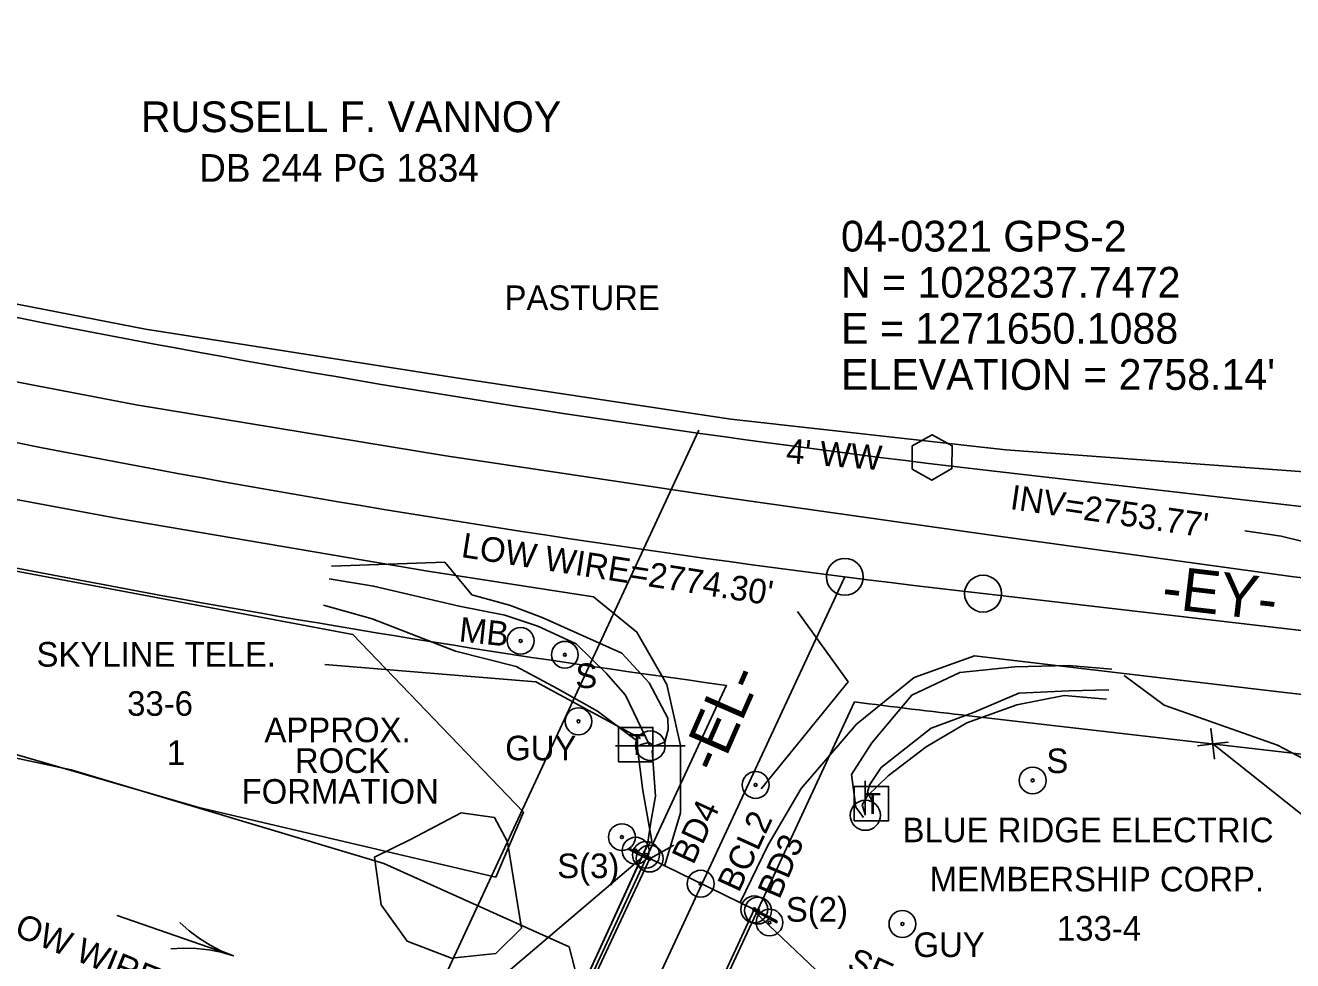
# Model space of a CAD drawing. Extents: x 1271070 to 1271913, y 1027587 to 1028435.
# Drawn here: x 1271502.6 to 1271708.8, y 1028155.9 to 1028308 of the extents above; entities that cross this region are included whole.
import ezdxf

# ---------------------------------------------------------------- set-up
doc = ezdxf.new("R2010")
doc.units = 0
for name, color, linetype in [('CTL Primary Horizontal and Vertical CELL', 7, 'Continuous'), ('CTL Primary Horizontal and Vertical Text', 7, 'Continuous'), ('Exist Horizontal Alignment', 7, 'Continuous'), ('Exist Horizontal Alignment Direction Label', 7, 'Continuous'), ('Exist Horizontal Alignment Point', 7, 'Continuous'), ('Exist Hydro Jurisdictional Stream or Body of Water', 7, 'Continuous'), ('Exist Hydro River Flow Arrow CELL', 7, 'Continuous'), ('Exist Other Culture Anchor (Guy Wire) CELL', 7, 'Continuous'), ('Exist Other Culture Anchor (Guy Wire) Text', 7, 'Continuous'), ('Exist Other Culture Area Outline', 7, 'Continuous'), ('Exist Other Culture Area Outline Text', 7, 'Continuous'), ('Exist Other Culture Fence Line', 7, 'Continuous'), ('Exist Other Culture Fence Line Text', 7, 'Continuous'), ('Exist Other Culture Located Object CELL', 7, 'Continuous'), ('Exist Other Culture Located Object Leader', 7, 'Continuous'), ('Exist Other Culture Located Object Text', 7, 'Continuous'), ('Exist Other Culture Sign CELL', 7, 'Continuous'), ('Exist Other Culture Sign Text', 7, 'Continuous'), ('Exist Property Corner CELL', 7, 'Continuous'), ('Exist Property Deed Book Text', 7, 'Continuous'), ('Exist Property Line', 7, 'Continuous'), ('Exist Property Owner Text', 7, 'Continuous'), ('Exist Right of Way Line', 7, 'Continuous'), ('Exist Roads EOP', 7, 'Continuous'), ('Exist Roads Soil', 7, 'Continuous'), ('Exist Structure Major Bridge WW', 7, 'Continuous'), ('Exist Structure Major Deck Tunnel Box Culvert', 7, 'Continuous'), ('Exist Structure Minor Pipes CMP 18 Inch Invert', 7, 'Continuous'), ('Exist Structure Minor Pipes CMP 18 Inch Leader', 7, 'Continuous'), ('Exist Utilities Other Located Object CELL', 7, 'Continuous'), ('Exist Utilities Other Located Object Leader', 7, 'Continuous'), ('Exist Utilities Other Located Object Text', 7, 'Continuous'), ('Exist Utilities Power Pole CELL', 7, 'Continuous'), ('Exist Utilities Power Pole Text', 7, 'Continuous'), ('Exist Utilities Telephone Pedestal CELL', 7, 'Continuous'), ('Exist Utilities Telephone Pole CELL', 7, 'Continuous'), ('Exist Utilities Telephone Pole Leader', 7, 'Continuous'), ('Exist Utilities Telephone Pole Text', 7, 'Continuous'), ('Exist Utilities Telephone UG Cable SUE LOS C', 7, 'Continuous'), ('Exist Vegetation Woods Line', 7, 'Continuous'), ('Exist Vegetation Woods Line Text', 7, 'Continuous')]:
    doc.layers.add(name, color=color, linetype=linetype)

msp = doc.modelspace()

# ---------------------------------------------------------------- linework, layer by layer
at = {"layer": 'CTL Primary Horizontal and Vertical CELL'}
msp.add_line((1271650.11, 1028237.75), (1271650.11, 1028237.75), dxfattribs=at)
msp.add_lwpolyline([(1271646.88, 1028239.62), (1271650.13, 1028241.43), (1271653.38, 1028239.64), (1271653.33, 1028235.92), (1271650.08, 1028234.03), (1271646.88, 1028235.84)], close=True, dxfattribs=at)
at = {"layer": 'Exist Horizontal Alignment'}
for p, q in [((1271563.09, 1028136.63), (1271612.17, 1028242.18)), ((1271586.84, 1028112.76), (1271635.92, 1028218.31)), ((1271812.09, 1028197.82), (1271658.4, 1028215.59))]:
    msp.add_line(p, q, dxfattribs=at)
msp.add_arc((1271888.09, 1030202.35), 2000, 256.46543, 263.40535, dxfattribs=at)
at = {"layer": 'Exist Horizontal Alignment Point'}
for centre in [(1271635.92, 1028218.31), (1271658.4, 1028215.58)]:
    msp.add_circle(centre, 3, dxfattribs=at)
at = {"layer": 'Exist Hydro Jurisdictional Stream or Body of Water'}
msp.add_lwpolyline([(1271304.7, 1028214.03), (1271358.66, 1028206.9), (1271411.07, 1028198.58), (1271456, 1028198.43), (1271510.08, 1028186.94), (1271560.93, 1028171.69), (1271591.08, 1028158.12), (1271592.88, 1028151.16), (1271591.46, 1028148.01), (1271611.09, 1028139.56), (1271653.5, 1028127.81), (1271692.8, 1028106.61), (1271731.61, 1028109.95), (1271774.25, 1028123.55), (1271810.26, 1028145.38)], dxfattribs=at)
at = {"layer": 'Exist Hydro River Flow Arrow CELL'}
msp.add_line((1271527.02, 1028159.94), (1271527.02, 1028159.94), dxfattribs=at)
msp.add_lwpolyline([(1271527.77, 1028162.1), (1271529.29, 1028160.73), (1271530.95, 1028159.49), (1271532.72, 1028158.37), (1271534.56, 1028157.4), (1271536.47, 1028156.66), (1271517.57, 1028163.21), (1271536.47, 1028156.66), (1271534.51, 1028157.26), (1271532.47, 1028157.64), (1271530.39, 1028157.86), (1271528.31, 1028157.9), (1271526.27, 1028157.78)], dxfattribs=at)
at = {"layer": 'Exist Other Culture Anchor (Guy Wire) CELL'}
for centre, radius in [((1271592.6, 1028194.81), 2.18), ((1271592.6, 1028194.81), 0.24), ((1271645.29, 1028161.84), 2.18), ((1271645.29, 1028161.84), 0.24)]:
    msp.add_circle(centre, radius, dxfattribs=at)
at = {"layer": 'Exist Other Culture Area Outline'}
msp.add_lwpolyline([(1271573.53, 1028179.92), (1271565.29, 1028175.58), (1271559.41, 1028172.73), (1271560.52, 1028164.98), (1271564.73, 1028159.03), (1271571.92, 1028156.3), (1271579.17, 1028157.04), (1271583.32, 1028161.14), (1271581.03, 1028175.21), (1271578.92, 1028179.18), (1271573.53, 1028179.92)], dxfattribs=at)
at = {"layer": 'Exist Other Culture Fence Line'}
msp.add_lwpolyline([(1271329.58, 1028308.04), (1271377.99, 1028292.04), (1271424.8, 1028279.04), (1271475.06, 1028267.76), (1271522.2, 1028258.62), (1271572.4, 1028250.75), (1271617.37, 1028243.97), (1271662.13, 1028238.98), (1271711.39, 1028235.36)], dxfattribs=at)
at = {"layer": 'Exist Other Culture Located Object CELL'}
for centre, radius in [((1271583.19, 1028207.9), 2.18), ((1271583.19, 1028207.9), 0.24), ((1271604.18, 1028172.48), 2.18), ((1271604.18, 1028172.48), 0.24), ((1271612.47, 1028168.39), 2.18), ((1271612.47, 1028168.39), 0.24), ((1271621.19, 1028164.22), 2.18), ((1271621.19, 1028164.22), 0.24)]:
    msp.add_circle(centre, radius, dxfattribs=at)
at = {"layer": 'Exist Other Culture Located Object Leader'}
msp.add_line((1271604.35, 1028172.53), (1271608.12, 1028174.64), dxfattribs=at)
for points in [[(1271602.98, 1028172.65), (1271578.23, 1028151.61)], [(1271621.42, 1028163.66), (1271631.18, 1028154.39)]]:
    msp.add_lwpolyline(points, dxfattribs=at)
at = {"layer": 'Exist Other Culture Sign CELL'}
for centre, radius in [((1271590.38, 1028205.64), 2.18), ((1271590.38, 1028205.64), 0.24), ((1271666.47, 1028185.19), 2.18), ((1271666.47, 1028185.19), 0.24), ((1271599.67, 1028175.97), 2.18), ((1271599.67, 1028175.97), 0.24), ((1271601.9, 1028173.76), 2.18), ((1271603.58, 1028173.09), 2.18), ((1271601.9, 1028173.76), 0.24), ((1271603.58, 1028173.09), 0.24), ((1271621.8, 1028164.02), 2.18), ((1271623.67, 1028162.08), 2.18), ((1271621.8, 1028164.02), 0.24), ((1271623.67, 1028162.08), 0.24)]:
    msp.add_circle(centre, radius, dxfattribs=at)
at = {"layer": 'Exist Property Corner CELL'}
msp.add_line((1271695.75, 1028191.13), (1271695.75, 1028191.13), dxfattribs=at)
msp.add_lwpolyline([(1271693.27, 1028190.85), (1271698.23, 1028191.42), (1271695.75, 1028191.13), (1271695.46, 1028193.62), (1271696.04, 1028188.65)], dxfattribs=at)
at = {"layer": 'Exist Property Line'}
msp.add_line((1271695.75, 1028191.13), (1271753.17, 1028145.62), dxfattribs=at)
at = {"layer": 'Exist Right of Way Line'}
for p, q in [((1271814.39, 1028217.68), (1271660.7, 1028235.45)), ((1271577.77, 1028116.98), (1271616.68, 1028200.67)), ((1271595.91, 1028108.55), (1271637.48, 1028197.96)), ((1271809.79, 1028177.95), (1271656.1, 1028195.72))]:
    msp.add_line(p, q, dxfattribs=at)
for radius, start, end in [(1980, 256.46543, 263.40535), (2020, 256.46543, 262.27844), (2020, 262.87329, 263.40535)]:
    msp.add_arc((1271888.09, 1030202.35), radius, start, end, dxfattribs=at)
at = {"layer": 'Exist Roads EOP'}
for points in [[(1271326.12, 1028295.81), (1271374.93, 1028279.7), (1271422.05, 1028266.63), (1271472.3, 1028255.59), (1271520.64, 1028246.3), (1271571.03, 1028237.98), (1271615.64, 1028231.31), (1271659.72, 1028225.08), (1271708.96, 1028218.32), (1271759.42, 1028212.65), (1271812.87, 1028207.39)], [(1271319.45, 1028277.54), (1271369.22, 1028260.92), (1271417.71, 1028247.94), (1271468.48, 1028236.99), (1271517.72, 1028227.81), (1271568.11, 1028219.26), (1271595.03, 1028215.07), (1271602.11, 1028209.33), (1271606.99, 1028200.81), (1271609.21, 1028190.89), (1271609.19, 1028179.92), (1271606.63, 1028171.4)], [(1271618.92, 1028165.36), (1271623.45, 1028174.71), (1271628.8, 1028183.88), (1271637.83, 1028194.35), (1271647.2, 1028201.96), (1271657.01, 1028205.46), (1271707.02, 1028199.56), (1271757.47, 1028193.87), (1271811.32, 1028188.24)]]:
    msp.add_lwpolyline(points, dxfattribs=at)
at = {"layer": 'Exist Roads Soil'}
msp.add_lwpolyline([(1271777.75, 1028128), (1271763.67, 1028141.08), (1271744.44, 1028163.01), (1271728.78, 1028179.1), (1271706.28, 1028190.93), (1271687.87, 1028197.46), (1271681.36, 1028202.26)], dxfattribs=at)
at = {"layer": 'Exist Structure Major Bridge WW'}
for p, q in [((1271600.89, 1028174.14), (1271604.14, 1028172.65)), ((1271621.27, 1028164.22), (1271624.87, 1028162.34))]:
    msp.add_line(p, q, dxfattribs=at)
for points in [[(1271600.89, 1028174.14), (1271600.79, 1028173.94), (1271602.93, 1028172.86), (1271604.01, 1028172.34)], [(1271621.17, 1028163.99), (1271622.61, 1028163.3), (1271624.84, 1028162.05), (1271624.87, 1028162.34)]]:
    msp.add_lwpolyline(points, dxfattribs=at)
at = {"layer": 'Exist Structure Major Deck Tunnel Box Culvert'}
msp.add_lwpolyline([(1271573.86, 1028107.56), (1271604.18, 1028172.48), (1271621.19, 1028164.22), (1271591.17, 1028099.34), (1271573.86, 1028107.56)], dxfattribs=at)
at = {"layer": 'Exist Structure Minor Pipes CMP 18 Inch Leader'}
msp.add_lwpolyline([(1271714.59, 1028223.05), (1271706.89, 1028224.91), (1271700.96, 1028225.78)], dxfattribs=at)
at = {"layer": 'Exist Utilities Other Located Object CELL'}
for radius in [2.18, 0.24]:
    msp.add_circle((1271621.41, 1028184.46), radius, dxfattribs=at)
at = {"layer": 'Exist Utilities Other Located Object Leader'}
msp.add_lwpolyline([(1271622.33, 1028183.83), (1271636.44, 1028201.23), (1271628.23, 1028212.7)], dxfattribs=at)
at = {"layer": 'Exist Utilities Power Pole CELL'}
for q in [(1271639.25, 1028185.15), (1271639.25, 1028179.53)]:
    msp.add_line((1271639.25, 1028179.53), q, dxfattribs=at)
msp.add_circle((1271639.25, 1028179.53), 2.45, dxfattribs=at)
at = {"layer": 'Exist Utilities Telephone Pedestal CELL'}
for p, q in [((1271601.84, 1028191.07), (1271601.84, 1028191.07)), ((1271640.16, 1028181.46), (1271640.16, 1028181.46))]:
    msp.add_line(p, q, dxfattribs=at)
for points in [[(1271599.12, 1028188.24), (1271604.71, 1028188.24), (1271604.71, 1028193.83), (1271599.12, 1028193.83), (1271599.12, 1028188.24)], [(1271637.44, 1028178.63), (1271643.03, 1028178.63), (1271643.03, 1028184.23), (1271637.44, 1028184.23), (1271637.44, 1028178.63)]]:
    msp.add_lwpolyline(points, dxfattribs=at)
at = {"layer": 'Exist Utilities Telephone Pole CELL'}
for p, q in [((1271598.61, 1028190.85), (1271609.95, 1028190.85)), ((1271604.29, 1028190.85), (1271604.29, 1028190.85))]:
    msp.add_line(p, q, dxfattribs=at)
msp.add_circle((1271604.29, 1028190.85), 2.41, dxfattribs=at)
at = {"layer": 'Exist Utilities Telephone Pole Leader'}
msp.add_lwpolyline([(1271602.67, 1028192.01), (1271585.68, 1028201.23), (1271551.33, 1028204.04)], dxfattribs=at)
at = {"layer": 'Exist Utilities Telephone UG Cable SUE LOS C'}
for points in [[(1271604.93, 1028190.78), (1271606.63, 1028191.4), (1271607.16, 1028193.48), (1271607.13, 1028195.31), (1271604.08, 1028201.07), (1271599.63, 1028205.92), (1271586.69, 1028211.7), (1271581.37, 1028213.7), (1271575.27, 1028215.4), (1271570.84, 1028220.72), (1271552.44, 1028220.07)], [(1271552.03, 1028218.01), (1271559.27, 1028216.8), (1271573.19, 1028213.54), (1271580.61, 1028212.07), (1271586.01, 1028210.31), (1271592.23, 1028207.4), (1271597.08, 1028202.67), (1271600.27, 1028199.08), (1271604.16, 1028190.93)], [(1271602.03, 1028191.68), (1271595.71, 1028196.47), (1271589.15, 1028200.13), (1271582.45, 1028203.74), (1271572.57, 1028206.2), (1271559.02, 1028211.51), (1271551.11, 1028213.69)], [(1271679.33, 1028203.31), (1271672.32, 1028203.9), (1271663.55, 1028203.66), (1271654.6, 1028202.75), (1271646.8, 1028199.07), (1271640.3, 1028191.29), (1271636.98, 1028186.15), (1271637.72, 1028180.84), (1271638.97, 1028179.17)], [(1271639.23, 1028179.64), (1271638.74, 1028181.25), (1271639.59, 1028182.7), (1271642.95, 1028185.97), (1271649.17, 1028190.64), (1271655.74, 1028194.57), (1271663.89, 1028197.5), (1271671.58, 1028199.01), (1271678.5, 1028198.41)], [(1271678.84, 1028199.96), (1271672.41, 1028199.76), (1271664.2, 1028199.38), (1271656.83, 1028196.26), (1271649.97, 1028193.7), (1271641.84, 1028187.29), (1271640, 1028184.55), (1271639.62, 1028183.32), (1271640.29, 1028181.86)], [(1271604.59, 1028190.07), (1271605.13, 1028182.66), (1271604.35, 1028178.41), (1271603.81, 1028174.75), (1271587.49, 1028139.09), (1271572.77, 1028107.28), (1271570.73, 1028103.97), (1271551.65, 1028073.57)], [(1271602.19, 1028190.37), (1271603.06, 1028183.53), (1271604.53, 1028175.31), (1271603.71, 1028174.47), (1271587.48, 1028139.09), (1271572.81, 1028107.42), (1271571.29, 1028103.78), (1271552.27, 1028073.84)], [(1271604.66, 1028190.97), (1271604.02, 1028191.37), (1271602.58, 1028190.99)]]:
    msp.add_lwpolyline(points, dxfattribs=at)
at = {"layer": 'Exist Vegetation Woods Line'}
msp.add_lwpolyline([(1271320.34, 1028265.26), (1271388.96, 1028245.21), (1271486.11, 1028222.06), (1271555.88, 1028208.95), (1271583.64, 1028180.02), (1271579.16, 1028169.47), (1271530.83, 1028180.79), (1271472.23, 1028197.76), (1271434.45, 1028197.76), (1271374.7, 1028207.41), (1271327.66, 1028217.82), (1271304.15, 1028229.39)], dxfattribs=at)

# ---------------------------------------------------------------- texts
at = {"layer": 'CTL Primary Horizontal and Vertical Text'}
for s, p in [('04-0321 GPS-2', (1271635.3, 1028271.24)), ('N = 1028237.7472', (1271635.3, 1028263.74)), ('E = 1271650.1088', (1271635.3, 1028256.24)), ("ELEVATION = 2758.14'", (1271635.3, 1028248.74))]:
    msp.add_text(s, height=5, dxfattribs=at).set_placement(p)
at = {"layer": 'Exist Horizontal Alignment Direction Label'}
for s, rotation, p in [('-EY-', 353.3445, (1271687.28, 1028213.26)), ('-EL-', 66.3177, (1271615.39, 1028186.04))]:
    msp.add_text(s, height=7, rotation=rotation, dxfattribs=at).set_placement(p)
at = {"layer": 'Exist Other Culture Anchor (Guy Wire) Text'}
for p in [(1271580.68, 1028188.47), (1271647.08, 1028156.47)]:
    msp.add_text('GUY', height=4, dxfattribs=at).set_placement(p)
at = {"layer": 'Exist Other Culture Area Outline Text'}
for s, p in [('APPROX.', (1271541.52, 1028191.42)), ('ROCK', (1271546.47, 1028186.42)), ('FORMATION', (1271537.8, 1028181.41))]:
    msp.add_text(s, height=4, dxfattribs=at).set_placement(p)
at = {"layer": 'Exist Other Culture Fence Line Text'}
msp.add_text("4' WW", height=4, rotation=355.5898, dxfattribs=at).set_placement((1271626.27, 1028236.86))
at = {"layer": 'Exist Other Culture Located Object Text'}
for s, rotation, p in [('MB', 353.9483, (1271573.05, 1028207.82)), ('BD4', 65.2363, (1271611.27, 1028171.32)), ('BCL2', 65.3988, (1271618.68, 1028166.81)), ('BD3', 66.9326, (1271625.27, 1028165.71)), ('SEAT=', 335.6702, (1271636.06, 1028154.47))]:
    msp.add_text(s, height=4, rotation=rotation, dxfattribs=at).set_placement(p)
at = {"layer": 'Exist Other Culture Sign Text'}
for s, p in [('S', (1271592.09, 1028200.23)), ('S', (1271668.7, 1028186.39)), ('S(3)', (1271589.14, 1028169.3)), ('S(2)', (1271626.33, 1028162.21))]:
    msp.add_text(s, height=4, dxfattribs=at).set_placement(p)
at = {"layer": 'Exist Property Deed Book Text'}
msp.add_text('DB 244 PG 1834', height=4.5, dxfattribs=at).set_placement((1271530.9, 1028282.59))
at = {"layer": 'Exist Property Owner Text'}
msp.add_text('RUSSELL F. VANNOY', height=5, dxfattribs=at).set_placement((1271521.43, 1028290.66))
at = {"layer": 'Exist Structure Minor Pipes CMP 18 Inch Invert'}
msp.add_text("INV=2753.77'", height=4, rotation=351.6705, dxfattribs=at).set_placement((1271662.66, 1028229.36))
at = {"layer": 'Exist Utilities Other Located Object Text'}
for s, rotation, p in [("LOW WIRE=2774.30'", 351.0887, (1271573.39, 1028221.56)), ("LOW WIRE=2785.96'", 337.9808, (1271497.9, 1028161.11))]:
    msp.add_text(s, height=4, rotation=rotation, dxfattribs=at).set_placement(p)
at = {"layer": 'Exist Utilities Power Pole Text'}
for s, p in [('BLUE RIDGE ELECTRIC', (1271645.31, 1028175.14)), ('MEMBERSHIP CORP.', (1271649.72, 1028167.14)), ('133-4', (1271670.42, 1028159.14))]:
    msp.add_text(s, height=4, dxfattribs=at).set_placement(p)
at = {"layer": 'Exist Utilities Telephone Pedestal CELL'}
for p in [(1271600.71, 1028189.35), (1271639.03, 1028179.75)]:
    msp.add_text('T', height=3.42, dxfattribs=at).set_placement(p)
at = {"layer": 'Exist Utilities Telephone Pole Text'}
for s, p in [('SKYLINE TELE.', (1271504.45, 1028203.71)), ('33-6', (1271519.19, 1028195.71)), ('1', (1271525.65, 1028187.71))]:
    msp.add_text(s, height=4, dxfattribs=at).set_placement(p)
at = {"layer": 'Exist Vegetation Woods Line Text'}
msp.add_text('PASTURE', height=4, dxfattribs=at).set_placement((1271580.57, 1028261.72))

doc.saveas('drawing.dxf')
